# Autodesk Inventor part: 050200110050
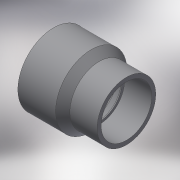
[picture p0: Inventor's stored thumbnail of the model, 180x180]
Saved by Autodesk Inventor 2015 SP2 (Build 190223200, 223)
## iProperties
Created: 2017-10
Part Number: 050200110050
Material: Generic
Description: PLASSON REDUCER SOCKET M.F.110(90)50 CEMENTED
Document SubType Name: Modeling
Designer: KIM
Density: 1 g/cm^3
Appearance: Default
Author: KIM
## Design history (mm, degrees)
derived "050200.ipt"
feature "Solid1::050200.ipt"
tag "TaggingFeature1"
body "Solid1"
other parameters: "d0" = 117, "d1" = 61, "d2" = 31, "d3" = 51, "d5" = 61, "d8" = 45, "d9" = 7.75297, "d12" = 0.9, "L_" = 61, "l_" = 51, "l_1" = 31, "E_" = 61, "H_" = 117, "d11" = 7.75297
